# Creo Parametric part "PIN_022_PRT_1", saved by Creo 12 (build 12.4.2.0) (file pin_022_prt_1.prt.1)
Units: Custom; MM, KILOGRAM, SECS

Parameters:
  PTC_WM_ITERATION = "0"
  PTC_WM_VERSION = "-.0"
  PTC_WM_LIFECYCLE_STATE = "In Work"
  PTC_WM_LIFECYCLE = "MO_CADDocument"
  PTC_WM_CREATED_BY = "Maximilian Roepper (Z0017RMS: MO)"
  PTC_WM_CREATED_ON = "18-Sep-26 11:36:42 AM"
  PTC_WM_MODIFIED_BY = "Maximilian Roepper (Z0017RMS: MO)"
  PTC_WM_MODIFIED_ON = "18-Sep-26 11:36:46 AM"
  PDMLINKNUMBER = "PDM000071455082"
  PTC_WM_NAME = "pin_022_prt_1.prt"
  PTC_WM_NUMBER = "PDM000071455082"

Other parameters: WEIGHT, WEIGHT_FACTOR, WEIGHT_ADD, _MASS_TEMP, _DIFF_TEMP, MC_ERRORS, SUPPLIER

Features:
  1. coordinate system
  2. datum plane "PRT_YZ"
  3. datum plane "PRT_XY"
  4. datum plane "PRT_XZ"
  5. coordinate system
  6. datum axis
  7. datum axis
  8. datum axis
  9. coordinate system
  10. imported feature
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
Other named items: PRT, SIEMENS_MO, DRW_VIEW_ORG, PRT_X, PRT_Y, PRT_Z, CS0, ROUGH_GROB

Layers: 00_STD_CSYS-KSYS, 01_STD_PLANES-EBENEN, 02_STD_AXES-ACHSEN, 03_STD_CSYS-KSYS, 24_IMPORT_FEAT-IMPORT_KE

Surfaces: 9 plane, 1 cylinder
